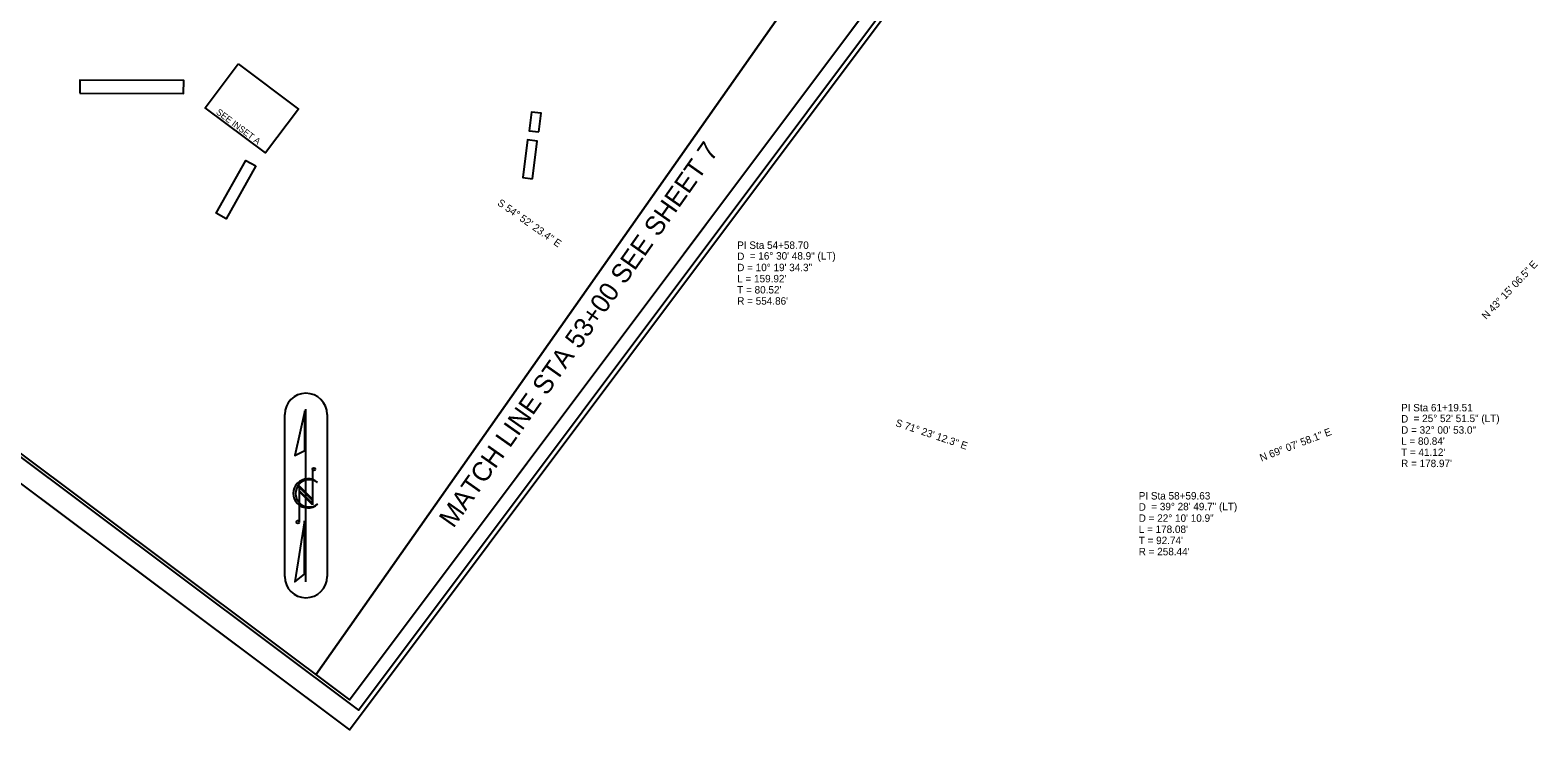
# Model space of a CAD drawing. Extents: x 928111 to 937215, y 684180 to 686530.
# Drawn here: x 931236 to 932656, y 684180 to 684839 of the extents above; entities that cross this region are included whole.
import ezdxf

# ---------------------------------------------------------------- set-up
doc = ezdxf.new("R2010")
doc.units = 0
for name, color, linetype in [('Exist Horizontal Alignment Curve and Spiral Data', 7, 'Continuous'), ('Exist Horizontal Alignment Direction Label', 7, 'Continuous'), ('Exist Horizontal Alignment Station Label', 7, 'Continuous'), ('Matchline', 7, 'Continuous'), ('Matchline Text', 7, 'Continuous'), ('Prop DSN Text', 7, 'Continuous'), ('Sheet Cutting Line CELL', 7, 'Continuous'), ('Sheet Layout Plan Border', 7, 'Continuous'), ('Sheet Plan CELL', 7, 'Continuous'), ('Sheet Plan Layout CELL', 7, 'Continuous'), ('Sheet Plot Border Inside CELL', 7, 'Continuous'), ('Sheet Plot Border Outside CELL', 7, 'Continuous')]:
    doc.layers.add(name, color=color, linetype=linetype)

msp = doc.modelspace()

# ---------------------------------------------------------------- linework, layer by layer
at = {"layer": 'Exist Horizontal Alignment Station Label'}
for p, q in [((931476, 684324.5), (931476, 684477)), ((931516, 684477), (931516, 684324.5))]:
    msp.add_line(p, q, dxfattribs=at)
for centre, start, end in [((931496, 684477), 90, 180), ((931496, 684477), 0, 90), ((931496, 684324.5), 180, 270), ((931496, 684324.5), 270, 0)]:
    msp.add_arc(centre, 20, start, end, dxfattribs=at)
at = {"layer": 'Matchline'}
msp.add_line((931505.3, 684232), (931987.9, 684918.1), dxfattribs=at)
at = {"layer": 'Prop DSN Text'}
for points in [[(931432.1, 684807.1), (931488.9, 684764.5), (931458, 684723.3), (931401.2, 684765.9)], [(931283.2, 684779.7), (931380.8, 684779.3), (931380.9, 684791.4), (931283.3, 684791.8)], [(931715.2, 684743.2), (931717.5, 684760.7), (931708.4, 684761.8), (931706.2, 684744.3)], [(931709.2, 684699), (931713.8, 684734.5), (931704.7, 684735.6), (931700.1, 684700.2)], [(931448.8, 684711.1), (931420.9, 684661.4), (931411.6, 684666.6), (931439.5, 684716.3)]]:
    msp.add_lwpolyline(points, close=True, dxfattribs=at)
at = {"layer": 'Sheet Cutting Line CELL'}
msp.add_line((930189.7, 685189.6), (931537, 684180.1), dxfattribs=at)
at = {"layer": 'Sheet Layout Plan Border'}
msp.add_line((931987.9, 684918.1), (931505.3, 684232), dxfattribs=at)
at = {"layer": 'Sheet Plan CELL'}
for p, q in [((931496, 684319.5), (931496, 684482)), ((931502.2, 684425.5), (931502.2, 684392.1)), ((931502.2, 684397.3), (931489.7, 684409.8)), ((931489.7, 684409.8), (931489.7, 684375.9)), ((931502.2, 684396.1), (931489.7, 684408.5)), ((931489.7, 684408.5), (931489.7, 684405.5)), ((931502.2, 684393.1), (931489.7, 684405.5)), ((931489.7, 684405.5), (931502.2, 684393.1)), ((931502.2, 684392.1), (931489.7, 684404.6)), ((931506.8, 684413.1), (931506.9, 684412.9)), ((931502.2, 684393.1), (931502.2, 684396.1))]:
    msp.add_line(p, q, dxfattribs=at)
for points in [[(932166.5, 685048.6), (930966.1, 685948.1), (930336.5, 685107.8), (931536.9, 684208.3)], [(931494.9, 684480.6), (931485.6, 684438.4), (931494.9, 684443.1)], [(931494.7, 684376.8), (931485.5, 684319.5), (931494.7, 684326.8)]]:
    msp.add_lwpolyline(points, close=True, dxfattribs=at)
for centre in [(931503.5, 684425.5), (931488.4, 684375.8)]:
    msp.add_circle(centre, 1.32, dxfattribs=at)
for centre, radius, start, end in [((931497.8, 684402.8), 13.7, 47.84, 312.3941), ((931499.1, 684402.8), 12.8, 53.095, 308.6287)]:
    msp.add_arc(centre, radius, start, end, dxfattribs=at)
at = {"layer": 'Sheet Plan Layout CELL'}
msp.add_lwpolyline([(930966.1, 685948.1), (930336.5, 685107.8), (931536.9, 684208.3), (932039.7, 684879.4), (931848.2, 685022.8), (931975, 685192.1)], close=True, dxfattribs=at)
at = {"layer": 'Sheet Plot Border Inside CELL'}
msp.add_lwpolyline([(930212.1, 685197.8), (931545.4, 684198.8), (932178, 685043.1), (930844.7, 686042.1)], close=True, dxfattribs=at)
at = {"layer": 'Sheet Plot Border Outside CELL'}
msp.add_lwpolyline([(930189.7, 685189.6), (931537, 684180.1), (932193.6, 685056.4), (930846.3, 686065.9)], close=True, dxfattribs=at)

# ---------------------------------------------------------------- texts
at = {"layer": 'Exist Horizontal Alignment Curve and Spiral Data'}
for s, p in [('PI Sta 54+58.70', (931902, 684633)), ('D', (931902, 684622.5)), ('= 16%%d 30\' 48.9" (LT)', (931913.8, 684622.9)), ('D = 10%%d 19\' 34.3"', (931902, 684612)), ("L = 159.92'", (931902, 684601.5)), ("T = 80.52'", (931902, 684591)), ("R = 554.86'", (931902, 684580.5)), ('PI Sta 61+19.51', (932527, 684480)), ('D', (932527, 684469.5)), ('= 25%%d 52\' 51.5" (LT)', (932538.8, 684469.9)), ('D = 32%%d 00\' 53.0"', (932527, 684459)), ("T = 41.12'", (932527, 684438)), ("L = 80.84'", (932527, 684448.5)), ("R = 178.97'", (932527, 684427.5)), ('PI Sta 58+59.63', (932280, 684397)), ('D', (932280, 684386.5)), ('= 39%%d 28\' 49.7" (LT)', (932291.8, 684386.9)), ('D = 22%%d 10\' 10.9"', (932280, 684376)), ("L = 178.08'", (932280, 684365.5)), ("T = 92.74'", (932280, 684355)), ("R = 258.44'", (932280, 684344.5))]:
    msp.add_text(s, height=7, dxfattribs=at).set_placement(p)
at = {"layer": 'Exist Horizontal Alignment Direction Label'}
for s, rotation, p in [('S 54%%d 52\' 23.4" E', 324.8732, (931675.6, 684674.8)), ('N 43%%d 15\' 06.5" E', 46.7482, (932607.2, 684566)), ('S 71%%d 23\' 12.3" E', 341.3867, (932050.4, 684466.4)), ('N 69%%d 07\' 58.1" E', 20.8672, (932395.5, 684432.7))]:
    msp.add_text(s, height=7, rotation=rotation, dxfattribs=at).set_placement(p)
at = {"layer": 'Matchline Text'}
msp.add_text('MATCH LINE STA 53+00 SEE SHEET 7', height=18, rotation=54.8616, dxfattribs=at).set_placement((931634.8, 684369.3))
at = {"layer": 'Prop DSN Text'}
msp.add_text('SEE INSET A', height=6, rotation=323.1562, dxfattribs=at).set_placement((931410.9, 684760.6))

doc.saveas('drawing.dxf')
